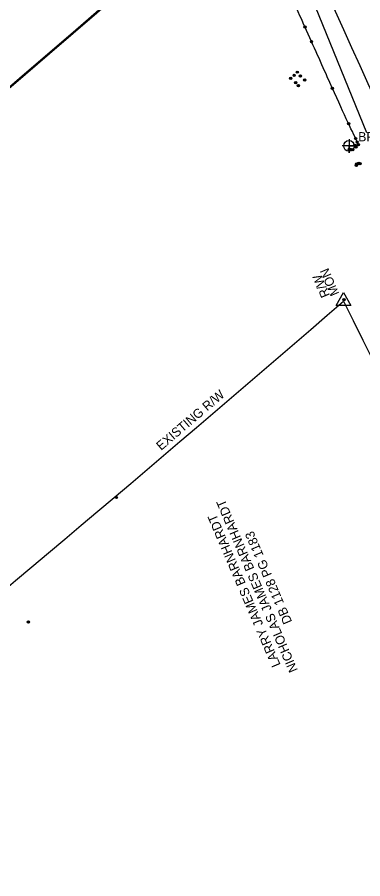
# Model space of a CAD drawing. Extents: x 1550153 to 1552579, y 809637 to 812160.
# Drawn here: x 1551716.6 to 1551868, y 810285.6 to 810663.3 of the extents above; entities that cross this region are included whole.
import ezdxf

# ---------------------------------------------------------------- set-up
doc = ezdxf.new("R2010")
doc.units = 0
for name, color, linetype in [('Default', 7, 'Continuous'), ('E_NCDOT_Horizontal_Alignment_Curve', 7, 'Continuous'), ('E_NCDOT_Horizontal_Alignment_Tick_Label', 7, 'Continuous'), ('Exist Property Text', 7, 'Continuous'), ('Exist Right of Way Line', 7, 'Continuous'), ('Exist Right of Way Line Text', 7, 'Continuous'), ('Exist Right of Way Monument CELL', 7, 'Continuous'), ('Exist Right of Way Monument Text', 7, 'Continuous'), ('Exist Roads EOP Other', 7, 'Continuous'), ('Exist Structure Major Bridge Seat Cogo Point CELL', 7, 'Continuous'), ('Exist Utilities Telephone UG Cable SUE LOS C', 7, 'Continuous')]:
    doc.layers.add(name, color=color, linetype=linetype)

# ---------------------------------------------------------------- blocks, each defined once
blk = doc.blocks.new('SurveyPointCell')
at = {"layer": 'Default'}
for p, q in [((-0.5, 0), (0.5, 0)), ((0, -0.5), (0, 0.5))]:
    blk.add_line(p, q, dxfattribs=at)
blk.add_circle((0, 0), 0.5, dxfattribs=at)

msp = doc.modelspace()

# ---------------------------------------------------------------- linework, layer by layer
at = {"layer": 'Default'}
msp.add_line((1551861.95, 810606.88), (1551861.95, 810606.88), dxfattribs=at)
msp.add_arc((1544558.52, 818987.58), 11000, 308.905285, 313.48368, dxfattribs=at)
msp.add_arc((1544558.52, 818987.58), 11000, 308.905285, 313.48368, dxfattribs=at)
at = {"layer": 'E_NCDOT_Horizontal_Alignment_Curve'}
for centre, radius, start, end in [((1544245.73, 819324.67), 11459.16, 307.933611, 313.133611), ((1544245.73, 819324.67), 11459.16, 307.933611, 313.133611), ((1554277.17, 811742.97), 2650, 199.47344, 205.4841), ((1554277.17, 811742.97), 2650, 199.47344, 205.4841)]:
    msp.add_arc(centre, radius, start, end, dxfattribs=at)
at = {"layer": 'E_NCDOT_Horizontal_Alignment_Tick_Label'}
msp.add_arc((1544558.52, 818987.58), 11000, 308.905285, 313.48368, dxfattribs=at)
at = {"layer": 'Exist Right of Way Line'}
for centre, radius, start, end in [((1544245.55, 819324.92), 11626.16, 307.933611, 310.911902), ((1554685.69, 811929.93), 3150, 206.2071, 211.76221)]:
    msp.add_arc(centre, radius, start, end, dxfattribs=at)
at = {"layer": 'Exist Right of Way Monument CELL'}
msp.add_line((1551859.5, 810538.83), (1551859.5, 810538.83), dxfattribs=at)
msp.add_lwpolyline([(1551856.25, 810536.94), (1551859.5, 810542.58), (1551862.75, 810536.94)], close=True, dxfattribs=at)
at = {"layer": 'Exist Roads EOP Other'}
msp.add_line((1551865.52, 810608.61), (1551864.83, 810610.13), dxfattribs=at)
msp.add_line((1551865.52, 810608.61), (1551864.83, 810610.13), dxfattribs=at)
msp.add_open_spline([(1551864.83, 810610.13), (1551863.85, 810612.31), (1551860.28, 810619.56), (1551853.04, 810635.92), (1551842.19, 810659.92), (1551829.81, 810688.31), (1551817.52, 810717.53), (1551805.7, 810746.3), (1551794.16, 810775.4), (1551783.02, 810804.5), (1551773.45, 810830.52), (1551767.56, 810846.7), (1551765.33, 810853.14)], degree=3, dxfattribs=at)
msp.add_open_spline([(1551864.83, 810610.13), (1551863.85, 810612.31), (1551860.28, 810619.56), (1551853.04, 810635.92), (1551842.19, 810659.92), (1551829.81, 810688.31), (1551817.52, 810717.53), (1551805.7, 810746.3), (1551794.16, 810775.4), (1551783.02, 810804.5), (1551773.45, 810830.52), (1551767.56, 810846.7), (1551765.33, 810853.14)], degree=3, dxfattribs=at)
at = {"layer": 'Exist Structure Major Bridge Seat Cogo Point CELL'}
msp.add_lwpolyline([(1551861.95, 810609.88), (1551861.95, 810603.88), (1551861.95, 810606.88), (1551864.95, 810606.88), (1551858.95, 810606.88)], dxfattribs=at)
msp.add_circle((1551861.95, 810606.88), 2.34, dxfattribs=at)
at = {"layer": 'Exist Utilities Telephone UG Cable SUE LOS C'}
msp.add_line((1551770.5, 810856.61), (1551869.65, 810612.8), dxfattribs=at)

# ---------------------------------------------------------------- block references
at = {"layer": 'Default'}
for p in [(1551842.67, 810659.01), (1551842.67, 810659.01), (1551845.52, 810652.56), (1551845.52, 810652.56), (1551837.93, 810637.79), (1551837.93, 810637.79), (1551839.26, 810639.2), (1551839.26, 810639.2), (1551840.68, 810637.58), (1551840.68, 810637.58), (1551836.39, 810636.54), (1551836.39, 810636.54), (1551838.6, 810634.64), (1551838.6, 810634.64), (1551839.8, 810633.31), (1551839.8, 810633.31), (1551842.56, 810635.74), (1551842.56, 810635.74), (1551854.7, 810632.14), (1551854.7, 810632.14), (1551861.76, 810616.61), (1551861.76, 810616.61), (1551864.43, 810607.09), (1551864.43, 810607.09), (1551864.83, 810610.13), (1551864.83, 810610.13), (1551865.52, 810608.61), (1551865.52, 810608.61), (1551866.08, 810607.41), (1551866.08, 810607.41), (1551862.01, 810605.33), (1551862.01, 810605.33), (1551862.51, 810605.37), (1551862.51, 810605.37), (1551863.56, 810605.22), (1551863.56, 810605.22), (1551864.98, 810606.46), (1551864.98, 810606.46), (1551866.2, 810599.25), (1551866.2, 810599.25), (1551865.2, 810598.31), (1551865.2, 810598.31), (1551865.35, 810599.01), (1551865.35, 810599.01), (1551866.75, 810599.04), (1551866.75, 810599.04), (1551859.71, 810539.41), (1551859.72, 810539.42), (1551760.08, 810452.75), (1551760.09, 810452.75), (1551721.52, 810398.24), (1551721.53, 810398.25)]:
    msp.add_blockref('SurveyPointCell', p, dxfattribs=at)

# ---------------------------------------------------------------- texts
msp.add_text("BRIDGE SEAT=727.65'", height=4.02, dxfattribs=at).set_placement((1551865.97, 810608.89))
at = {"layer": 'Exist Property Text'}
for s, p in [('NICHOLAS JAMES BARNHARDT', (1551839.59, 810377.1)), ('LARRY JAMES BARNHARDT', (1551832.05, 810379.41)), ('DB 1128 PG 1183', (1551837.09, 810398.28))]:
    msp.add_text(s, height=4.02, rotation=113.1736, dxfattribs=at).set_placement(p)
at = {"layer": 'Exist Right of Way Line Text'}
msp.add_text('EXISTING R/W', height=4.02, rotation=40.5183, dxfattribs=at).set_placement((1551779.62, 810473.17))
at = {"layer": 'Exist Right of Way Monument Text'}
for s, p in [('MON', (1551857.73, 810542.15)), ('R/W', (1551853.65, 810541.39))]:
    msp.add_text(s, height=4.02, rotation=113.1736, dxfattribs=at).set_placement(p)

doc.saveas('drawing.dxf')
